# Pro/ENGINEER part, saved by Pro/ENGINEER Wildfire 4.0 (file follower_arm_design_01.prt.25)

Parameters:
  METRIC = "NO"

Other parameters: PITCH, DRILL_DIAMETER, THREAD_DIAMETER, THREADS_PER_INCH, THREAD_DEPTH, THREAD_LENGTH, DRILL_POINT_ANGLE, DRILL_DEPTH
